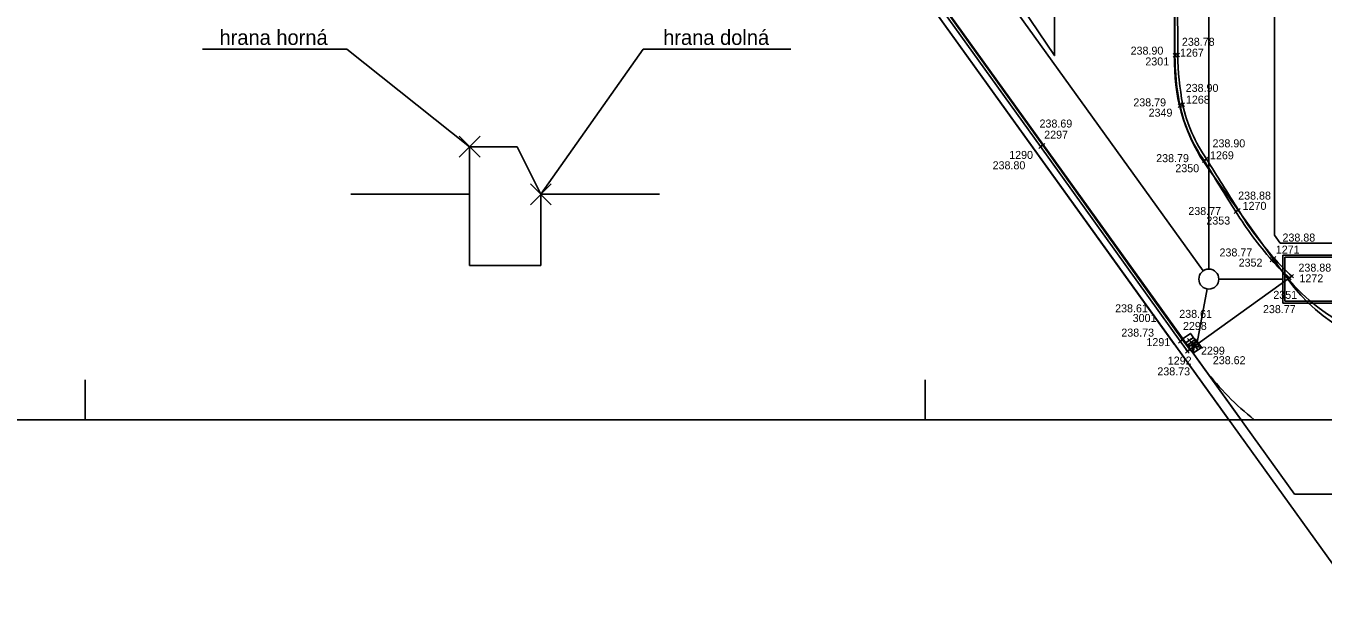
# Model space of a CAD drawing. Extents: x -264222 to -263676, y -1242344 to -1242060.
# Drawn here: x -264183 to -264118.1, y -1242315 to -1242285.6 of the extents above; entities that cross this region are included whole.
import ezdxf

# ---------------------------------------------------------------- set-up
doc = ezdxf.new("R2010")
doc.units = 0
for name, color, linetype in [('BODY_CISLO', 7, 'Continuous'), ('BODY_SYMBOL', 7, 'Continuous'), ('BODY_VYSKA', 7, 'Continuous'), ('BODY_VYSKY_UV', 7, 'Continuous'), ('KOORDINACNA_SITUACIA_DSP', 7, 'Continuous'), ('PROJEKT_DRS_OBRUBNIKY_KOMUNIKACIE', 7, 'Continuous'), ('PROJEKT_DRS_TDZ_VODOROVNE', 7, 'Continuous'), ('PROJEKT_DRS_UV_STAVBY', 7, 'Continuous'), ('RAM_NA_TLAC_8xA4_1-200', 7, 'Continuous'), ('ROZHRANIE_SO_20-3_a_20-1', 7, 'Continuous'), ('SCHEMA', 7, 'Continuous'), ('SO_20-3_OBRUBNIKY_DOLNA_HRANA', 7, 'Continuous'), ('SO_20-3_OBRUBNIKY_HORNA_HRANA', 7, 'Continuous'), ('ULICNA_VPUST_POKLOP', 7, 'Continuous')]:
    doc.layers.add(name, color=color, linetype=linetype)

msp = doc.modelspace()

# ---------------------------------------------------------------- linework, layer by layer
at = {"layer": 'BODY_SYMBOL'}
for p, q in [((-264125.639, -1242287.139), (-264125.463, -1242286.963)), ((-264125.463, -1242287.139), (-264125.639, -1242286.963)), ((-264125.498, -1242287.121), (-264125.322, -1242286.945)), ((-264125.322, -1242287.121), (-264125.498, -1242286.945)), ((-264125.39, -1242289.649), (-264125.214, -1242289.473)), ((-264125.214, -1242289.649), (-264125.39, -1242289.473)), ((-264125.251, -1242289.599), (-264125.075, -1242289.423)), ((-264125.075, -1242289.599), (-264125.251, -1242289.423)), ((-264132.36, -1242291.701), (-264132.184, -1242291.525)), ((-264132.184, -1242291.701), (-264132.36, -1242291.525)), ((-264132.236, -1242291.629), (-264132.06, -1242291.453)), ((-264132.06, -1242291.629), (-264132.236, -1242291.453)), ((-264124.175, -1242292.405), (-264123.999, -1242292.229)), ((-264123.999, -1242292.405), (-264124.175, -1242292.229)), ((-264124.057, -1242292.32), (-264123.881, -1242292.144)), ((-264123.881, -1242292.32), (-264124.057, -1242292.144)), ((-264122.593, -1242294.956), (-264122.417, -1242294.78)), ((-264122.417, -1242294.956), (-264122.593, -1242294.78)), ((-264122.464, -1242294.875), (-264122.288, -1242294.699)), ((-264122.288, -1242294.875), (-264122.464, -1242294.699)), ((-264120.684, -1242297.275), (-264120.508, -1242297.099)), ((-264120.508, -1242297.275), (-264120.684, -1242297.099)), ((-264120.792, -1242297.38), (-264120.616, -1242297.204)), ((-264120.616, -1242297.38), (-264120.792, -1242297.204)), ((-264119.916, -1242298.268), (-264119.74, -1242298.092)), ((-264119.74, -1242298.268), (-264119.916, -1242298.092)), ((-264119.796, -1242298.181), (-264119.62, -1242298.005)), ((-264119.62, -1242298.181), (-264119.796, -1242298.005)), ((-264125.373, -1242301.435), (-264125.197, -1242301.259)), ((-264125.197, -1242301.435), (-264125.373, -1242301.259)), ((-264125.253, -1242301.353), (-264125.077, -1242301.177)), ((-264125.077, -1242301.353), (-264125.253, -1242301.177)), ((-264124.922, -1242301.386), (-264124.746, -1242301.21)), ((-264124.746, -1242301.386), (-264124.922, -1242301.21)), ((-264124.896, -1242301.85), (-264124.72, -1242301.674)), ((-264124.72, -1242301.85), (-264124.896, -1242301.674)), ((-264125.014, -1242301.934), (-264124.838, -1242301.758)), ((-264124.838, -1242301.934), (-264125.014, -1242301.758))]:
    msp.add_line(p, q, dxfattribs=at)
at = {"layer": 'KOORDINACNA_SITUACIA_DSP'}
for p, q in [((-264204.694, -1242191.482), (-264122.859, -1242305.266)), ((-264204.078, -1242191.482), (-264122.243, -1242305.266)), ((-264123.854, -1242237.976), (-264123.854, -1242297.736)), ((-264152.757, -1242258.05), (-264124.146, -1242297.83)), ((-264152.757, -1242258.05), (-264124.146, -1242297.83)), ((-264125.568, -1242287.467), (-264125.568, -1242270.982)), ((-264123.874, -1242292.722), (-264120.268, -1242297.737)), ((-264120.568, -1242296.035), (-264120.282, -1242296.432)), ((-264120.154, -1242297.036), (-264120.154, -1242299.436)), ((-264115.254, -1242297.036), (-264120.154, -1242297.036)), ((-264115.354, -1242297.136), (-264120.054, -1242297.136)), ((-264120.054, -1242297.136), (-264120.054, -1242299.336)), ((-264123.354, -1242298.236), (-264120.154, -1242298.236)), ((-264124.444, -1242301.414), (-264123.946, -1242298.728)), ((-264120.154, -1242299.436), (-264115.254, -1242299.436)), ((-264120.054, -1242299.336), (-264115.354, -1242299.336)), ((-264124.925, -1242301.537), (-264124.69, -1242301.368)), ((-264124.633, -1242301.943), (-264124.925, -1242301.537)), ((-264124.69, -1242301.368), (-264124.398, -1242301.774)), ((-264124.69, -1242301.368), (-264124.633, -1242301.943)), ((-264124.69, -1242301.368), (-264124.633, -1242301.943)), ((-264124.398, -1242301.774), (-264124.69, -1242301.368)), ((-264124.398, -1242301.774), (-264124.633, -1242301.943)), ((-264124.633, -1242301.943), (-264124.398, -1242301.774))]:
    msp.add_line(p, q, dxfattribs=at)
for points in [[(-264204.694, -1242191.482), (-264137.78, -1242284.52), (-264125.581, -1242301.482)], [(-264120.568, -1242296.035), (-264120.568, -1242271.189), (-264120.568, -1242271.189)], [(-264096.03, -1242296.432), (-264120.018, -1242296.432), (-264120.282, -1242296.432)]]:
    msp.add_lwpolyline(points, dxfattribs=at)
for centre, radius in [((-264123.854, -1242298.236), 0.5), ((-264124.462, -1242301.513), 0.1)]:
    msp.add_circle(centre, radius, dxfattribs=at)
for centre, start, end in [((-264116.568, -1242287.467), 180, 215.72401), ((-264112.961, -1242292.482), 215.72401, 270)]:
    msp.add_arc(centre, 9, start, end, dxfattribs=at)
at = {"layer": 'PROJEKT_DRS_OBRUBNIKY_KOMUNIKACIE'}
for p, q in [((-264204.694, -1242191.482), (-264115.871, -1242314.982)), ((-264204.078, -1242191.482), (-264119.571, -1242308.982)), ((-264125.568, -1242287.467), (-264125.568, -1242270.982)), ((-264120.568, -1242296.035), (-264120.568, -1242271.189)), ((-264123.874, -1242292.722), (-264120.268, -1242297.737)), ((-264120.568, -1242296.035), (-264120.282, -1242296.432)), ((-264050.531, -1242308.982), (-264119.571, -1242308.982))]:
    msp.add_line(p, q, dxfattribs=at)
for points in [[(-264204.694, -1242191.482), (-264137.78, -1242284.52), (-264125.581, -1242301.482)], [(-263965.143, -1242296.432), (-264120.018, -1242296.432), (-264120.282, -1242296.432)]]:
    msp.add_lwpolyline(points, dxfattribs=at)
for centre, start, end in [((-264116.568, -1242287.467), 180, 215.72401), ((-264112.961, -1242292.482), 215.72401, 270)]:
    msp.add_arc(centre, 9, start, end, dxfattribs=at)
at = {"layer": 'PROJEKT_DRS_TDZ_VODOROVNE'}
msp.add_lwpolyline([(-264139.918, -1242274.696), (-264131.568, -1242287.061), (-264131.568, -1242277.056)], dxfattribs=at)
for centre, radius, start, end in [((-264112.56, -1242292.924), 9.068, 215.87399, 267.4682), ((-264112.435, -1242293.84), 14.642, 217.62012, 231.29143)]:
    msp.add_arc(centre, radius, start, end, dxfattribs=at)
at = {"layer": 'PROJEKT_DRS_UV_STAVBY'}
msp.add_lwpolyline([(-264124.633, -1242301.943), (-264124.925, -1242301.538), (-264124.519, -1242301.246), (-264124.227, -1242301.651), (-264124.633, -1242301.943), (-264124.519, -1242301.246), (-264124.925, -1242301.538), (-264124.227, -1242301.651)], dxfattribs=at)
at = {"layer": 'RAM_NA_TLAC_8xA4_1-200'}
for p, q in [((-264180.03, -1242305.266), (-264180.03, -1242303.266)), ((-264138.03, -1242305.266), (-264138.03, -1242303.266))]:
    msp.add_line(p, q, dxfattribs=at)
msp.add_lwpolyline([(-264222.03, -1242186.466), (-264054.03, -1242186.466), (-264054.03, -1242305.266), (-264222.03, -1242305.266)], close=True, dxfattribs=at)
at = {"layer": 'ROZHRANIE_SO_20-3_a_20-1'}
msp.add_line((-264124.926, -1242301.846), (-264119.708, -1242298.093), dxfattribs=at)
at = {"layer": 'SCHEMA'}
for p, q in [((-264152.131, -1242286.735), (-264157.25, -1242293.993)), ((-264152.131, -1242286.735), (-264144.745, -1242286.735)), ((-264161.334, -1242292.144), (-264160.285, -1242291.095)), ((-264160.285, -1242292.144), (-264161.334, -1242291.095)), ((-264160.809, -1242297.552), (-264160.809, -1242291.62)), ((-264160.809, -1242291.62), (-264158.436, -1242291.62)), ((-264158.436, -1242291.62), (-264157.25, -1242293.993)), ((-264157.774, -1242294.517), (-264156.725, -1242293.468)), ((-264156.725, -1242294.517), (-264157.774, -1242293.468)), ((-264164.369, -1242293.993), (-264166.742, -1242293.993)), ((-264160.809, -1242293.993), (-264164.369, -1242293.993)), ((-264157.25, -1242297.552), (-264157.25, -1242293.993)), ((-264153.69, -1242293.993), (-264157.25, -1242293.993)), ((-264151.317, -1242293.993), (-264153.69, -1242293.993)), ((-264160.809, -1242297.552), (-264157.25, -1242297.552))]:
    msp.add_line(p, q, dxfattribs=at)
msp.add_lwpolyline([(-264174.161, -1242286.735), (-264166.94, -1242286.735), (-264160.809, -1242291.62)], dxfattribs=at)
at = {"layer": 'SO_20-3_OBRUBNIKY_DOLNA_HRANA'}
for points in [[(-264179.08, -1242196.474), (-264200.47, -1242196.472), (-264195.765, -1242203.023), (-264189.923, -1242211.168), (-264184.11, -1242219.268), (-264178.281, -1242227.391), (-264171.252, -1242237.149), (-264164.83, -1242246.079), (-264158.406, -1242254.997), (-264151.981, -1242263.929), (-264145.549, -1242272.885), (-264139.496, -1242281.305), (-264132.148, -1242291.541), (-264125.165, -1242301.265), (-264124.808, -1242301.762)], [(-264125.585, -1242271.017), (-264125.561, -1242281.034), (-264125.551, -1242287.051)]]:
    msp.add_lwpolyline(points, dxfattribs=at)
for centre, major_axis, ratio, start_param, end_param in [((-264111.36, -1242286.915), (1.586, -14.312), 0.985444, 4.613033, 4.788424), ((-264117.781, -1242287.891), (3.336, -6.944), 0.999948, 4.482958, 4.876448), ((-263998.852, -1242215.853), (84.302, -140.139), 0.897217, 4.7183, 4.736655), ((-264106.585, -1242284.92), (11.187, -15.171), 0.995879, 4.635852, 4.796229), ((-264110.944, -1242288.545), (9.2, -9.413), 0.995723, 4.669382, 4.764177)]:
    msp.add_ellipse(centre, major_axis=major_axis, ratio=ratio, start_param=start_param, end_param=end_param, dxfattribs=at)
at = {"layer": 'SO_20-3_OBRUBNIKY_HORNA_HRANA'}
msp.add_line((-264125.435, -1242271.03), (-264125.41, -1242287.033), dxfattribs=at)
msp.add_lwpolyline([(-264204.226, -1242191.388), (-264204.22, -1242191.499), (-264200.55, -1242196.62), (-264195.884, -1242203.112), (-264190.046, -1242211.249), (-264184.226, -1242219.352), (-264178.398, -1242227.475), (-264171.378, -1242237.231), (-264164.951, -1242246.159), (-264158.525, -1242255.075), (-264152.106, -1242264.005), (-264145.671, -1242272.964), (-264139.631, -1242281.361), (-264132.272, -1242291.613), (-264125.285, -1242301.347), (-264124.926, -1242301.846)], dxfattribs=at)
for centre, major_axis, ratio, start_param, end_param in [((-264110.542, -1242286.806), (1.637, -14.996), 0.985568, 4.620267, 4.785533), ((-264117.568, -1242287.8), (2.992, -7.193), 0.999392, 4.539799, 4.923581), ((-264058.218, -1242251.717), (75.932, -123.334), 0.533241, 4.712594, 4.733384), ((-264107.502, -1242285.613), (10.173, -14.289), 0.99631, 4.646606, 4.817168), ((-264111.21, -1242288.87), (8.289, -9.444), 0.998043, 4.717107, 4.818155)]:
    msp.add_ellipse(centre, major_axis=major_axis, ratio=ratio, start_param=start_param, end_param=end_param, dxfattribs=at)
at = {"layer": 'ULICNA_VPUST_POKLOP'}
msp.add_line((-264124.834, -1242301.298), (-264124.834, -1242301.298), dxfattribs=at)
msp.add_lwpolyline([(-264125.039, -1242301.441), (-264125.182, -1242301.237), (-264124.773, -1242300.95), (-264124.486, -1242301.359), (-264124.895, -1242301.646), (-264125.039, -1242301.441), (-264124.629, -1242301.155)], dxfattribs=at)

# ---------------------------------------------------------------- texts
at = {"layer": 'BODY_CISLO'}
for s, p in [('1267', (-264125.295, -1242287.116)), ('2301', (-264127.029, -1242287.555)), ('1268', (-264125, -1242289.465)), ('2349', (-264126.865, -1242290.115)), ('2297', (-264132.085, -1242291.216)), ('1290', (-264133.835, -1242292.228)), ('1269', (-264123.796, -1242292.247)), ('2350', (-264125.529, -1242292.893)), ('1270', (-264122.166, -1242294.774)), ('2353', (-264123.979, -1242295.509)), ('1271', (-264120.507, -1242296.962)), ('2352', (-264122.365, -1242297.612)), ('1272', (-264119.325, -1242298.399)), ('2351', (-264120.631, -1242299.223)), ('3001', (-264127.662, -1242300.381)), ('2298', (-264125.149, -1242300.778)), ('1291', (-264126.974, -1242301.586)), ('2299', (-264124.247, -1242302.014)), ('1292', (-264125.907, -1242302.509))]:
    msp.add_text(s, height=0.4, dxfattribs=at).set_placement(p)
at = {"layer": 'BODY_VYSKA'}
for s, p in [('238.78', (-264125.202, -1242286.572)), ('238.90', (-264127.766, -1242287.015)), ('238.90', (-264125.012, -1242288.878)), ('238.79', (-264127.63, -1242289.601)), ('238.69', (-264132.319, -1242290.66)), ('238.90', (-264123.671, -1242291.648)), ('238.79', (-264126.488, -1242292.39)), ('238.80', (-264134.664, -1242292.746)), ('238.88', (-264122.388, -1242294.261)), ('238.77', (-264124.88, -1242295.031)), ('238.88', (-264120.173, -1242296.359)), ('238.77', (-264123.321, -1242297.103)), ('238.88', (-264119.374, -1242297.862)), ('238.61', (-264125.333, -1242300.174)), ('238.77', (-264121.149, -1242299.937)), ('238.73', (-264128.23, -1242301.111)), ('238.62', (-264123.656, -1242302.491)), ('238.73', (-264126.429, -1242303.049))]:
    msp.add_text(s, height=0.4, dxfattribs=at).set_placement(p)
at = {"layer": 'BODY_VYSKY_UV'}
msp.add_text('238.61', height=0.4, dxfattribs=at).set_placement((-264128.54, -1242299.898))
at = {"layer": 'SCHEMA'}
for s, p in [('hrana horná', (-264173.315, -1242286.528)), ('hrana dolná', (-264151.134, -1242286.528))]:
    msp.add_text(s, height=0.75, dxfattribs=at).set_placement(p)

doc.saveas('drawing.dxf')
